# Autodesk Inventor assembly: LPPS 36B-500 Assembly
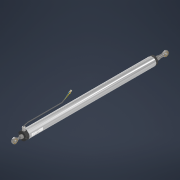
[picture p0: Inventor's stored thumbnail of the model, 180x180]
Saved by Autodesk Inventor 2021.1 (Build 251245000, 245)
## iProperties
Created: 2020-09
Part Number: LPPS 36B-500 Assembly
Document SubType Name: Assembly
Designer: J. Nielson
Author: J. Nielson
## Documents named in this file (3)
- C:\Users\Justin\Documents\CAD\The Sensor Connection\LPPS\LPPS-36B Series\3D\LPPS 36B-500\LPPS 36B-500 Assembly.iam
- C:\Users\Justin\Documents\CAD\The Sensor Connection\LPPS\LPPS-36B Series\3D\LPPS 36B-500\LPPS 36B-500_Shaft_Shrinkwrap.ipt
- C:\Users\Justin\Documents\CAD\The Sensor Connection\LPPS\LPPS-36B Series\3D\LPPS 36B-500\LPPS 36B-500_Shrinkwrap.ipt
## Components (2 placed, 2 different names)
1. LPPS 36B-500_Shaft_Shrinkwrap:1 — Mate:1, Cylindrical:1, Angle:1
2. LPPS 36B-500_Shrinkwrap:1 — Mate:1, Cylindrical:1
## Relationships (3: Mate 1, CylindricalJoint 1, Angle 1)
- Mate:1: LPPS 36B-500_Shaft_Shrinkwrap:1 ↔ LPPS 36B-500_Shrinkwrap:1
- Cylindrical:1: LPPS 36B-500_Shaft_Shrinkwrap:1 ↔ LPPS 36B-500_Shrinkwrap:1
- Angle:1: LPPS 36B-500_Shaft_Shrinkwrap:1
